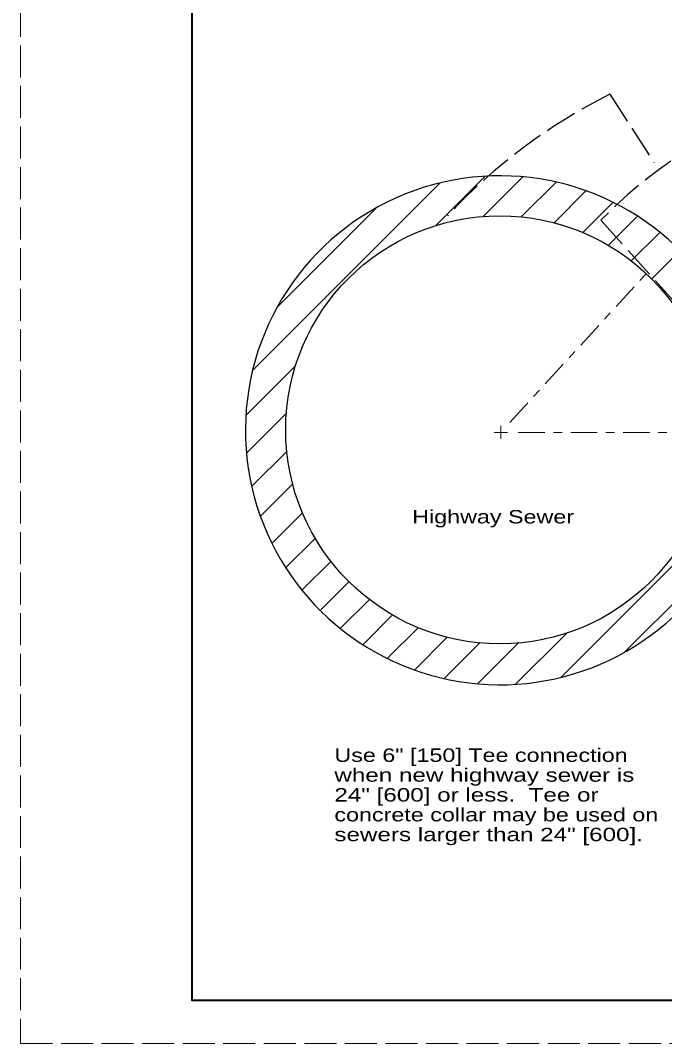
# Model space of a CAD drawing. Extents: x 1083.1 to 1117.1, y 719.4 to 741.4.
# Drawn here: x 1083.13 to 1090.62, y 719.35 to 731.26 of the extents above; entities that cross this region are included whole.
import ezdxf

# ---------------------------------------------------------------- set-up
doc = ezdxf.new("R2010")
doc.units = 0
doc.header["$LTSCALE"] = 0.062
doc.linetypes.add('DOT_DASHED', pattern=[7.7, 5, -1.2, 0.3, -1.2])
doc.linetypes.add('LONG_DASHED', pattern=[7.5, 6, -1.5])
doc.layers.add('1', color=7, linetype='Continuous', lineweight=13)

msp = doc.modelspace()

# ---------------------------------------------------------------- linework, layer by layer
at = {"layer": '1', "linetype": 'LONG_DASHED', "lineweight": 25}
for p, q in [((1089.98642, 730.40275), (1090.4975, 729.60533)), ((1089.88158, 728.9365), (1091.07208, 727.60925))]:
    msp.add_line(p, q, dxfattribs=at)
at = {"layer": '1'}
for p, q in [((1087.95467, 728.869), (1088.52867, 729.443)), ((1088.50892, 728.97558), (1088.97283, 729.43958)), ((1085.83367, 727.19583), (1088.00667, 729.36858)), ((1088.95433, 728.97342), (1089.35933, 729.37833)), ((1089.3315, 728.903), (1089.70508, 729.27658)), ((1089.66567, 728.7895), (1090.01908, 729.14283)), ((1086.12225, 727.93192), (1087.26267, 729.07233)), ((1089.96408, 728.64033), (1090.30508, 728.98133)), ((1090.23092, 728.45958), (1090.5655, 728.79408)), ((1090.4685, 728.2495), (1090.80167, 728.58275)), ((1085.75242, 726.667), (1086.32767, 727.24217)), ((1085.76042, 726.2275), (1086.2235, 726.69042)), ((1088.71658, 726.467), (1088.71658, 726.54292)), ((1088.63875, 726.467), (1088.79433, 726.467)), ((1088.71658, 726.467), (1088.71658, 726.39108)), ((1085.8205, 725.83992), (1086.22892, 726.24833)), ((1085.92075, 725.49258), (1086.298, 725.86983)), ((1086.05408, 725.17833), (1086.41075, 725.53492)), ((1089.41892, 723.6195), (1091.31233, 725.51267)), ((1086.21608, 724.89275), (1086.55967, 725.23617)), ((1090.15975, 723.91267), (1091.28925, 725.04208)), ((1086.40392, 724.633), (1086.74025, 724.96925)), ((1086.61625, 724.39767), (1086.95017, 724.73158)), ((1086.85242, 724.18633), (1087.18867, 724.5225)), ((1087.113, 723.99933), (1087.45625, 724.3425)), ((1087.39925, 723.838), (1087.755, 724.19358)), ((1087.71392, 723.705), (1088.09317, 724.08417)), ((1088.88892, 723.53708), (1089.48742, 724.1355)), ((1088.061, 723.60442), (1088.47717, 724.02058)), ((1088.447, 723.54283), (1088.9215, 724.01725))]:
    msp.add_line(p, q, dxfattribs=at)
at = {"layer": '1', "linetype": 'DOT_DASHED'}
for p, q in [((1088.82117, 726.58325), (1090.40817, 728.31392)), ((1088.91917, 726.467), (1093.80292, 726.467))]:
    msp.add_line(p, q, dxfattribs=at)
at = {"layer": '1', "linetype": 'LONG_DASHED'}
msp.add_lwpolyline([(1083.12642, 719.35408), (1117.12642, 719.35408), (1117.12642, 741.35408), (1083.12642, 741.35408)], close=True, dxfattribs=at)
at = {"layer": '1', "lineweight": 25}
msp.add_lwpolyline([(1116.62642, 719.85408), (1085.12642, 719.85408), (1085.12642, 740.85408)], dxfattribs=at)
at = {"layer": '1', "lineweight": 40}
msp.add_lwpolyline([(1085.12642, 740.85408), (1116.62642, 740.85408), (1116.62642, 719.85408), (1085.12642, 719.85408)], close=True, dxfattribs=at)
msp.add_lwpolyline([(1085.12642, 740.85408), (1116.62642, 740.85408), (1116.62642, 719.85408), (1085.12642, 719.85408)], close=True, dxfattribs=at)
at = {"layer": '1', "linetype": 'LONG_DASHED', "lineweight": 25}
for centre, major_axis, start_param, end_param in [((1093.00167, 724.40433), (-6.71418, 0), 5.17813533, 5.53174825), ((1093.49182, 725.47113), (-5.00454, 0), 4.83363783, 5.51820357)]:
    msp.add_ellipse(centre, major_axis=major_axis, ratio=0.999895, start_param=start_param, end_param=end_param, dxfattribs=at)
at = {"layer": '1', "lineweight": 25}
msp.add_ellipse((1088.70626, 726.4909), major_axis=(2.96229, 0), ratio=0.999895, start_param=0.68963883, end_param=5.5796092, dxfattribs=at)
msp.add_ellipse((1088.70428, 726.49659), major_axis=(2.49131, 0), ratio=0.999895, dxfattribs=at)

# ---------------------------------------------------------------- texts
at = {"layer": '1'}
for s, width, p in [('Highway Sewer', 1.3, (1087.68467, 725.40683)), ('Use 6" [150] Tee connection', 1.3, (1086.7795, 722.63192)), ('when new highway sewer is', 1.35, (1086.7795, 722.40117)), ('24" [600] or less.  Tee or', 1.35, (1086.7795, 722.17042)), ('concrete collar may be used on', 1.3, (1086.7795, 721.93967)), ('sewers larger than 24" [600].', 1.35, (1086.7795, 721.70892))]:
    msp.add_text(s, height=0.156, dxfattribs=dict(at, width=width)).set_placement(p)

doc.saveas('drawing.dxf')
